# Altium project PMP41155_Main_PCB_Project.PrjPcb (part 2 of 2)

## Sheet PMP41155_Main_Control.SchDoc
size 431 x 279 mm; Date: Not shown in title block; ApprovedBy: Not shown in title block; CheckedBy: Not shown in title block; Author: Not shown in title block; CompanyName: Not shown in title block; Engineer: Not shown in title block; Organization: Not shown in title block; Address1: Not shown in title block; Address2: Not shown in title block; Address3: Not shown in title block; Address4: Not shown in title block; DocumentNumber: 2; Revision: Use project parameter SCH_Rev; SheetNumber: 4; SheetTotal: 5; PageSetup: Record=PageOptions¦CenterHorizontal=True¦CenterVertical=True¦PrintScale=1.00¦XCorrection=1.00¦YCorrection=1.00¦PrintKind=0¦BorderSize=5000000¦LeftOffset=0¦BottomOffset=0¦Orientation=2¦PaperLength=1000¦PaperWidth=1000¦Scale=100¦PaperSource=15¦PrintQuality=600¦MediaType=1¦DitherType=10¦PaperKind=Letter¦PrintScaleMode=1
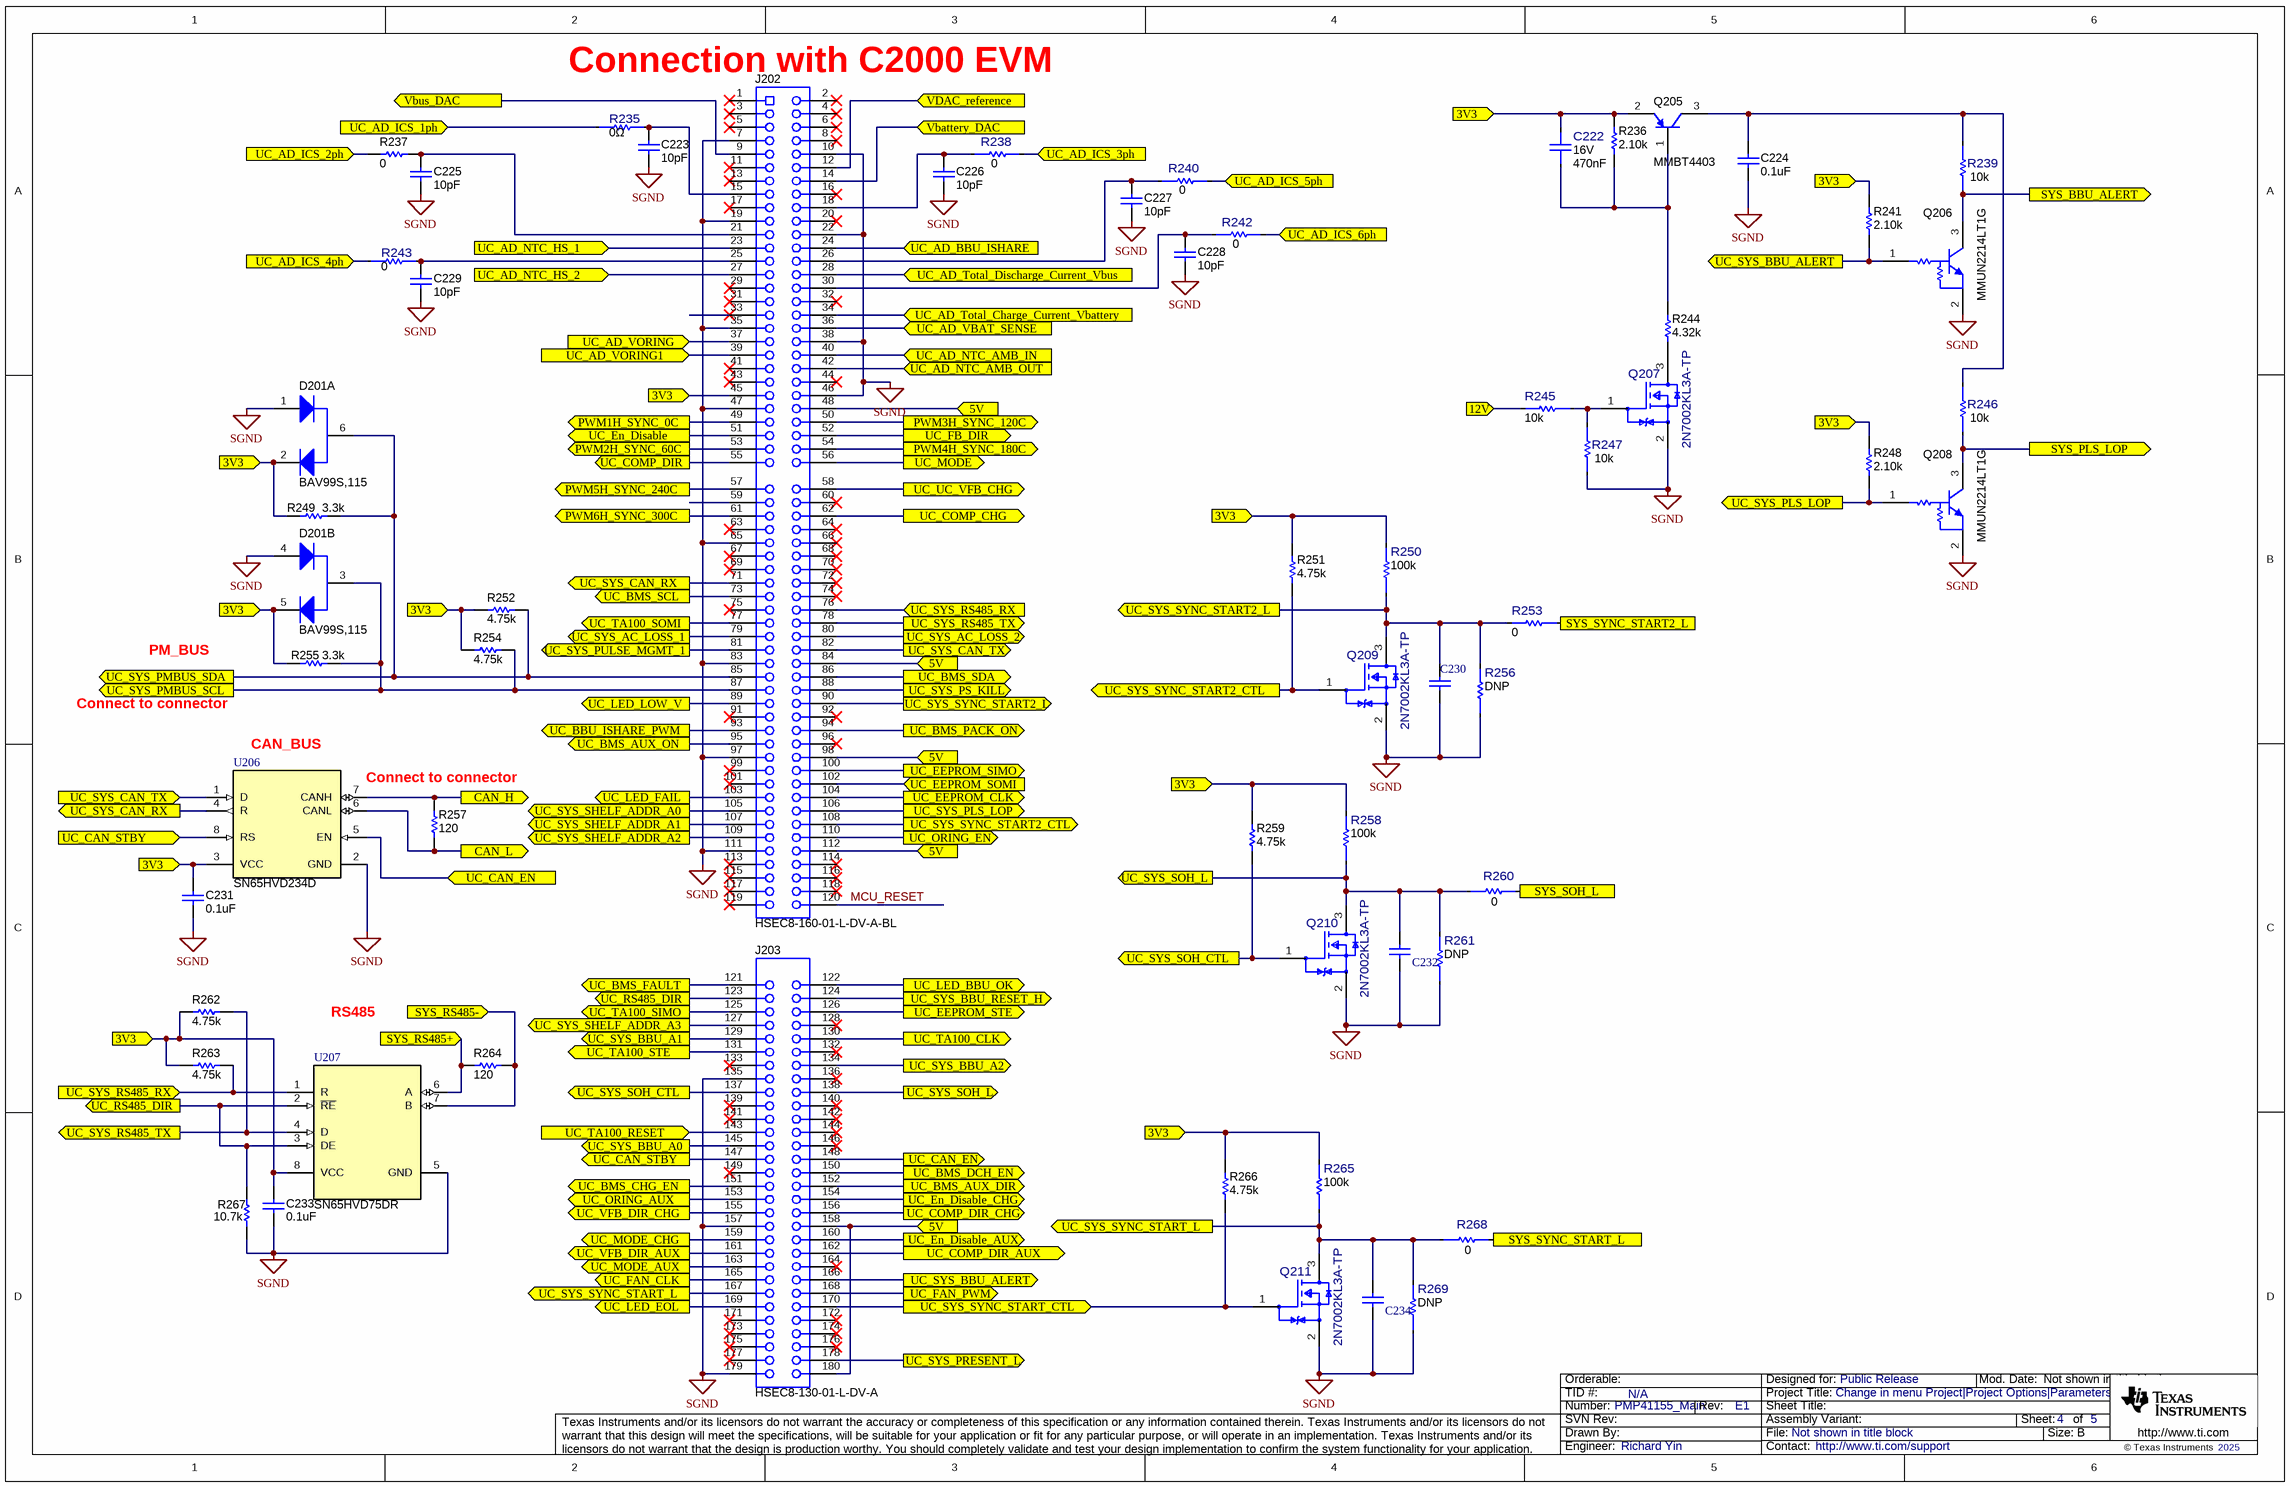
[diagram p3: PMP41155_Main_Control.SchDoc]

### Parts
C222  VDC_V: 16V  Cap_F: 470nF  [FP-C0603C474K4RAC7867_0603-MFG]  (hidden comment: C0603C474K4RAC7867)
C223  ValueDisplayed: 10pF  [0603]  (hidden comment: 0603ZC100KAT2A)
C224  ValueDisplayed: 0.1uF  [0402]  (hidden comment: CMP-0006623-2)
C225  ValueDisplayed: 10pF  [0603]  (hidden comment: 0603ZC100KAT2A)
C226  ValueDisplayed: 10pF  [0603]  (hidden comment: 0603ZC100KAT2A)
C227  ValueDisplayed: 10pF  [0603]  (hidden comment: 0603ZC100KAT2A)
C228  ValueDisplayed: 10pF  [0603]  (hidden comment: 0603ZC100KAT2A)
C229  ValueDisplayed: 10pF  [0603]  (hidden comment: 0603ZC100KAT2A)
C230  885012205001  [WCAP-CSGP_0402_L1W0.5H0.5]  (value not drawn)
C231  ValueDisplayed: 0.1uF  [0402]  (hidden comment: CMP-0006623-2)
C232  885012205001  [WCAP-CSGP_0402_L1W0.5H0.5]  (value not drawn)
C233  ValueDisplayed: 0.1uF  [0402]  (hidden comment: CMP-0006623-2)
C234  885012205001  [WCAP-CSGP_0402_L1W0.5H0.5]  (value not drawn)
D201  BAV99S,115  [SOT-363]  (parts A,B of 2)
J202  HSEC8-160-01-L-DV-A-BL  [controlCARD-120HSEC]
J203  HSEC8-130-01-L-DV-A  [controlCARD-180HSEC-60pinAddon]
Q205  MMBT4403  [SOT-23]
Q206  MMUN2214LT1G  [SOT-23]
Q207  2N7002KL3A-TP  [FP-2N7002KL3A-TP_DFN3-MFG]
Q208  MMUN2214LT1G  [SOT-23]
Q209  2N7002KL3A-TP  [FP-2N7002KL3A-TP_DFN3-MFG]
Q210  2N7002KL3A-TP  [FP-2N7002KL3A-TP_DFN3-MFG]
Q211  2N7002KL3A-TP  [FP-2N7002KL3A-TP_DFN3-MFG]
R235  value 0Ω  [FP-CR0603-10W-000T_0603-MFG]  (hidden comment: CR0603-10W-000T)
R236  ValueDisplayed: 2.10k  [0402]  (hidden comment: CRCW04022K10FKED)
R237  ValueDisplayed: 0  [0603]  (hidden comment: RC0603JR-070RL)
R238  Res_ohm: 0  [FP-CR0201PM0RS001_0201-MFG]  (hidden comment: CR0201PM0RS001)
R239  Res_ohm: 10k  [FP-ERJ-U02F1002X_0402-MFG]  (hidden comment: ERJ-U02F1002X)
R240  Res_ohm: 0  [FP-CR0201PM0RS001_0201-MFG]  (hidden comment: CR0201PM0RS001)
R241  ValueDisplayed: 2.10k  [0402]  (hidden comment: CRCW04022K10FKED)
R242  Res_ohm: 0  [FP-CR0201PM0RS001_0201-MFG]  (hidden comment: CR0201PM0RS001)
R243  value 0  [FP-WSL060300000ZEA9_0603-MFG]  (hidden comment: WSL060300000ZEA9)
R244  ValueDisplayed: 4.32k  [0402]  (hidden comment: CRCW04024K32FKED)
R245  Res_ohm: 10k  [FP-ERJ-U02F1002X_0402-MFG]  (hidden comment: ERJ-U02F1002X)
R246  Res_ohm: 10k  [FP-ERJ-U02F1002X_0402-MFG]  (hidden comment: ERJ-U02F1002X)
R247  Res_ohm: 10k  [FP-ERJ-U02F1002X_0402-MFG]  (hidden comment: ERJ-U02F1002X)
R248  ValueDisplayed: 2.10k  [0402]  (hidden comment: CRCW04022K10FKED)
R249  ValueDisplayed: 3.3k  [0402]  (hidden comment: CRCW04023K30JNED)
R250  Res_ohm: 100k  [FP-RC0402JR-07100KL_0402-MFG]  (hidden comment: RC0402JR-07100KL)
R251  ValueDisplayed: 4.75k  [0603]  (hidden comment: RC0603FR-074K75L)
R252  ValueDisplayed: 4.75k  [0603]  (hidden comment: RC0603FR-074K75L)
R253  Res_ohm: 0  [FP-ERJ-H2G0R00X_0402-MFG]  (hidden comment: ERJ-H2G0R00X)
R254  ValueDisplayed: 4.75k  [0603]  (hidden comment: RC0603FR-074K75L)
R255  ValueDisplayed: 3.3k  [0402]  (hidden comment: CRCW04023K30JNED)
R256  Res_ohm: DNP  [FP-ERJ-H2G0R00X_0402-MFG]  (hidden comment: ERJ-H2G0R00X)
R257  ValueDisplayed: 120  [0402]  (hidden comment: CRCW0402120RJNED)
R258  Res_ohm: 100k  [FP-RC0402JR-07100KL_0402-MFG]  (hidden comment: RC0402JR-07100KL)
R259  ValueDisplayed: 4.75k  [0603]  (hidden comment: RC0603FR-074K75L)
R260  Res_ohm: 0  [FP-JR0805X35E_0805-MFG]  (hidden comment: JR0805X35E)
R261  Res_ohm: DNP  [FP-JR0805X35E_0805-MFG]  (hidden comment: JR0805X35E)
R262  ValueDisplayed: 4.75k  [0603]  (hidden comment: RC0603FR-074K75L)
R263  ValueDisplayed: 4.75k  [0603]  (hidden comment: RC0603FR-074K75L)
R264  ValueDisplayed: 120  [0402]  (hidden comment: CRCW0402120RJNED)
R265  Res_ohm: 100k  [FP-RC0402JR-07100KL_0402-MFG]  (hidden comment: RC0402JR-07100KL)
R266  ValueDisplayed: 4.75k  [0603]  (hidden comment: RC0603FR-074K75L)
R267  ValueDisplayed: 10.7k  [0603]  (hidden comment: RC0603FR-0710K7L)
R268  Res_ohm: 0  [FP-JR0805X35E_0805-MFG]  (hidden comment: JR0805X35E)
R269  Res_ohm: DNP  [FP-JR0805X35E_0805-MFG]  (hidden comment: JR0805X35E)
U206  SN65HVD234D  [D0008A_N]
U207  SN65HVD75DR  [D0008A_N]

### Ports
3V3 (in), 5V (in), 12V (in), CAN_H (out), CAN_L (out), PWM1H_SYNC_0C (out), PWM2H_SYNC_60C (out), PWM3H_SYNC_120C (out), PWM4H_SYNC_180C (out), PWM5H_SYNC_240C (out), PWM6H_SYNC_300C (out), SYS_BBU_ALERT (out), SYS_PLS_LOP (out), SYS_RS485+ (in), SYS_RS485- (in), SYS_SOH_L (out), SYS_SYNC_START2_L (out), SYS_SYNC_START_L (out), UC_AD_BBU_ISHARE (in), UC_AD_ICS_1ph (in), UC_AD_ICS_2ph (in), UC_AD_ICS_3ph (in), UC_AD_ICS_4ph (in), UC_AD_ICS_5ph (in), UC_AD_ICS_6ph (in), UC_AD_NTC_AMB_IN (in), UC_AD_NTC_AMB_OUT (in), UC_AD_NTC_HS_1 (in), UC_AD_NTC_HS_2 (in), UC_AD_Total_Charge_Current_Vbattery (in), UC_AD_Total_Discharge_Current_Vbus (in), UC_AD_VBAT_SENSE (in), UC_AD_VORING1 (in), UC_AD_VORING (in), UC_BBU_ISHARE_PWM (out), UC_BMS_AUX_DIR (out), UC_BMS_AUX_ON (out), UC_BMS_CHG_EN (out), UC_BMS_DCH_EN (out), UC_BMS_FAULT (out), UC_BMS_PACK_ON (out), UC_BMS_SCL (out), UC_BMS_SDA (out), UC_CAN_EN (in), UC_CAN_EN (out), UC_CAN_STBY (in), UC_CAN_STBY (out), UC_COMP_CHG (out), UC_COMP_DIR (out), UC_COMP_DIR_AUX (out), UC_COMP_DIR_CHG (out), UC_EEPROM_CLK (out), UC_EEPROM_SIMO (out), UC_EEPROM_SOMI (in), UC_EEPROM_STE (out), UC_En_Disable (out), UC_En_Disable_AUX (out), UC_En_Disable_CHG (out), UC_FAN_CLK (out), UC_FAN_PWM (out), UC_FB_DIR (out), UC_LED_BBU_OK (out), UC_LED_EOL (out), UC_LED_FAIL (out), UC_LED_LOW_V (out), UC_MODE (out), UC_MODE_AUX (out), UC_MODE_CHG (out), UC_ORING_AUX (out), UC_ORING_EN (out), UC_RS485_DIR (out), UC_SYS_AC_LOSS_1 (out), UC_SYS_AC_LOSS_2 (out), UC_SYS_BBU_A0 (out), UC_SYS_BBU_A1 (out), UC_SYS_BBU_A2 (out), UC_SYS_BBU_ALERT (out), UC_SYS_BBU_RESET_H (out), UC_SYS_CAN_RX (out), UC_SYS_CAN_TX (in), UC_SYS_CAN_TX (out), UC_SYS_PLS_LOP (out), UC_SYS_PMBUS_SCL (out), UC_SYS_PMBUS_SDA (out), UC_SYS_PRESENT_L (out), UC_SYS_PS_KILL (out), UC_SYS_PULSE_MGMT_1 (out), UC_SYS_RS485_RX (in), UC_SYS_RS485_TX (out), UC_SYS_SHELF_ADDR_A0 (out), UC_SYS_SHELF_ADDR_A1 (out), UC_SYS_SHELF_ADDR_A2 (out), UC_SYS_SHELF_ADDR_A3 (out), UC_SYS_SOH_CTL (out), UC_SYS_SOH_L (out), UC_SYS_SYNC_START2_CTL (out), UC_SYS_SYNC_START2_L (out), UC_SYS_SYNC_START_CTL (out), UC_SYS_SYNC_START_L (out), UC_TA100_CLK (out), UC_TA100_RESET (in), UC_TA100_SIMO (out), UC_TA100_SOMI (out), UC_TA100_STE (out), UC_UC_VFB_CHG (out), UC_VFB_DIR_AUX (out), UC_VFB_DIR_CHG (out), Vbattery_DAC (in), Vbus_DAC (out), VDAC_reference (in)

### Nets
SGND: C223.2 C224.2 C225.2 C226.2 C227.2 C228.2 C229.2 C230.1 C231.2 C232.1 C233.2 C234.1 D201.1(A1) D201.4(A3) J202.7 J202.10 J202.19 J202.22 J202.35 J202.38 J202.46 J202.47 J202.65 J202.83 J202.97 J202.111 J203.135 J203.157 J203.179 Q206.2(E) Q207.2(S) Q208.2(E) Q209.2(S) Q210.2(S) Q211.2(S) R247.1 R256.1 R261.1 R267.1 R269.1 U206.2(GND) U207.5(GND)
3V3: C222.2 C231.1 C233.1 D201.2(K2) D201.5(K4) J202.45 Q205.2(E) R236.2 R241.2 R248.2 R249.1 R250.2 R251.2 R252.2 R254.2 R255.1 R258.2 R259.2 R262.2 R263.2 R265.2 R266.2 U206.3(VCC) U207.8(VCC) ; port 3V3
5V: J202.48 J202.84 J202.98 J202.112 J203.158 J203.180 ; port 5V
12V: R245.2 ; port 12V
CAN_H: R257.2 U206.7(CANH) ; port CAN_H
CAN_L: R257.1 U206.6(CANL) ; port CAN_L
MCU_RESET: J202.120
PWM1H_SYNC_0C: J202.49 ; port PWM1H_SYNC_0C
PWM2H_SYNC_60C: J202.53 ; port PWM2H_SYNC_60C
PWM3H_SYNC_120C: J202.50 ; port PWM3H_SYNC_120C
PWM4H_SYNC_180C: J202.54 ; port PWM4H_SYNC_180C
PWM5H_SYNC_240C: J202.57 ; port PWM5H_SYNC_240C
PWM6H_SYNC_300C: J202.61 ; port PWM6H_SYNC_300C
SYS_BBU_ALERT: Q206.3(C) R239.1 ; port SYS_BBU_ALERT
SYS_PLS_LOP: Q208.3(C) R246.1 ; port SYS_PLS_LOP
SYS_RS485+: R264.2 U207.6(A) ; port SYS_RS485+
SYS_RS485-: R264.1 U207.7(B) ; port SYS_RS485-
SYS_SOH_L: R260.2 ; port SYS_SOH_L
SYS_SYNC_START2_L: R253.1 ; port SYS_SYNC_START2_L
SYS_SYNC_START_L: R268.2 ; port SYS_SYNC_START_L
UC_AD_BBU_ISHARE: J202.24 ; port UC_AD_BBU_ISHARE
UC_AD_ICS_1ph: R235.1 ; port UC_AD_ICS_1ph
UC_AD_ICS_2ph: R237.1 ; port UC_AD_ICS_2ph
UC_AD_ICS_3ph: R238.2 ; port UC_AD_ICS_3ph
UC_AD_ICS_4ph: R243.1 ; port UC_AD_ICS_4ph
UC_AD_ICS_5ph: R240.2 ; port UC_AD_ICS_5ph
UC_AD_ICS_6ph: R242.2 ; port UC_AD_ICS_6ph
UC_AD_NTC_AMB_IN: J202.40 ; port UC_AD_NTC_AMB_IN
UC_AD_NTC_AMB_OUT: J202.42 ; port UC_AD_NTC_AMB_OUT
UC_AD_NTC_HS_1: J202.23 ; port UC_AD_NTC_HS_1
UC_AD_NTC_HS_2: J202.27 ; port UC_AD_NTC_HS_2
UC_AD_Total_Charge_Current_VBattery: J202.34 ; port UC_AD_Total_Charge_Current_Vbattery
UC_AD_Total_Discharge_Current_VBus: J202.28 ; port UC_AD_Total_Discharge_Current_Vbus
UC_AD_VBAT_SENSE: J202.36 ; port UC_AD_VBAT_SENSE
UC_AD_VORING: J202.37 ; port UC_AD_VORING
UC_AD_VORING1: J202.39 ; port UC_AD_VORING1
UC_BBU_ISHARE_PWM: J202.93 ; port UC_BBU_ISHARE_PWM
UC_BMS_AUX_DIR: J203.152 ; port UC_BMS_AUX_DIR
UC_BMS_AUX_ON: J202.95 ; port UC_BMS_AUX_ON
UC_BMS_CHG_EN: J203.151 ; port UC_BMS_CHG_EN
UC_BMS_DCH_EN: J203.150 ; port UC_BMS_DCH_EN
UC_BMS_FAULT: J203.121 ; port UC_BMS_FAULT
UC_BMS_PACK_ON: J202.94 ; port UC_BMS_PACK_ON
UC_BMS_SCL: J202.73 ; port UC_BMS_SCL
UC_BMS_SDA: J202.86 ; port UC_BMS_SDA
UC_CAN_EN: J203.148 U206.5(EN) ; port UC_CAN_EN
UC_CAN_STBY: J203.147 U206.8(RS) ; port UC_CAN_STBY
UC_COMP_CHG: J202.62 ; port UC_COMP_CHG
UC_COMP_DIR: J202.55 ; port UC_COMP_DIR
UC_COMP_DIR_AUX: J203.162 ; port UC_COMP_DIR_AUX
UC_COMP_DIR_CHG: J203.156 ; port UC_COMP_DIR_CHG
UC_EEPROM_CLK: J202.104 ; port UC_EEPROM_CLK
UC_EEPROM_SIMO: J202.100 ; port UC_EEPROM_SIMO
UC_EEPROM_SOMI: J202.102 ; port UC_EEPROM_SOMI
UC_EEPROM_STE: J203.126 ; port UC_EEPROM_STE
UC_En_Disable: J202.51 ; port UC_En_Disable
UC_En_Disable_AUX: J203.160 ; port UC_En_Disable_AUX
UC_En_Disable_CHG: J203.154 ; port UC_En_Disable_CHG
UC_FAN_CLK: J203.165 ; port UC_FAN_CLK
UC_FAN_PWM: J203.168 ; port UC_FAN_PWM
UC_FB_DIR: J202.52 ; port UC_FB_DIR
UC_LED_BBU_OK: J203.122 ; port UC_LED_BBU_OK
UC_LED_EOL: J203.169 ; port UC_LED_EOL
UC_LED_FAIL: J202.103 ; port UC_LED_FAIL
UC_LED_LOW_V: J202.89 ; port UC_LED_LOW_V
UC_MODE: J202.56 ; port UC_MODE
UC_MODE_AUX: J203.163 ; port UC_MODE_AUX
UC_MODE_CHG: J203.159 ; port UC_MODE_CHG
UC_ORING_AUX: J203.153 ; port UC_ORING_AUX
UC_ORING_EN: J202.110 ; port UC_ORING_EN
UC_RS485_DIR: J203.123 R267.2 U207.2(~{RE}) U207.3(DE) ; port UC_RS485_DIR
UC_SYS_AC_LOSS_1: J202.79 ; port UC_SYS_AC_LOSS_1
UC_SYS_AC_LOSS_2: J202.80 ; port UC_SYS_AC_LOSS_2
UC_SYS_BBU_A0: J203.145 ; port UC_SYS_BBU_A0
UC_SYS_BBU_A1: J203.129 ; port UC_SYS_BBU_A1
UC_SYS_BBU_A2: J203.134 ; port UC_SYS_BBU_A2
UC_SYS_BBU_ALERT: J203.166 Q206.1(B) R241.1 ; port UC_SYS_BBU_ALERT
UC_SYS_BBU_RESET_H: J203.124 ; port UC_SYS_BBU_RESET_H
UC_SYS_CAN_RX: J202.71 U206.4(R) ; port UC_SYS_CAN_RX
UC_SYS_CAN_TX: J202.82 U206.1(D) ; port UC_SYS_CAN_TX
UC_SYS_PLS_LOP: J202.106 Q208.1(B) R248.1 ; port UC_SYS_PLS_LOP
UC_SYS_PMBUS_SCL: D201.3(K3A4) J202.87 R254.1 R255.2 ; port UC_SYS_PMBUS_SCL
UC_SYS_PMBUS_SDA: D201.6(K1A2) J202.85 R249.2 R252.1 ; port UC_SYS_PMBUS_SDA
UC_SYS_Present_L: J203.178 ; port UC_SYS_PRESENT_L
UC_SYS_PS_KILL: J202.88 ; port UC_SYS_PS_KILL
UC_SYS_PULSE_MGMT_1: J202.81 ; port UC_SYS_PULSE_MGMT_1
UC_SYS_RS485_RX: J202.76 R263.1 U207.1(R) ; port UC_SYS_RS485_RX
UC_SYS_RS485_TX: J202.78 R262.1 U207.4(D) ; port UC_SYS_RS485_TX
UC_SYS_SHELF_ADDR_A0: J202.105 ; port UC_SYS_SHELF_ADDR_A0
UC_SYS_SHELF_ADDR_A1: J202.107 ; port UC_SYS_SHELF_ADDR_A1
UC_SYS_SHELF_ADDR_A2: J202.109 ; port UC_SYS_SHELF_ADDR_A2
UC_SYS_SHELF_ADDR_A3: J203.127 ; port UC_SYS_SHELF_ADDR_A3
UC_SYS_SOH_CTL: J203.137 Q210.1(G) R259.1 ; port UC_SYS_SOH_CTL
UC_SYS_SOH_L: C232.2 J203.138 Q210.3(D) R258.1 R260.1 R261.2 ; port UC_SYS_SOH_L
UC_SYS_SYNC_START2_CTL: J202.108 Q209.1(G) R251.1 ; port UC_SYS_SYNC_START2_CTL
UC_SYS_SYNC_START2_L: C230.2 J202.90 Q209.3(D) R250.1 R253.2 R256.2 ; port UC_SYS_SYNC_START2_L
UC_SYS_SYNC_START_CTL: J203.170 Q211.1(G) R266.1 ; port UC_SYS_SYNC_START_CTL
UC_SYS_SYNC_START_L: C234.2 J203.167 Q211.3(D) R265.1 R268.1 R269.2 ; port UC_SYS_SYNC_START_L
UC_TA100_CLK: J203.130 ; port UC_TA100_CLK
UC_TA100_RESET: J203.143 ; port UC_TA100_RESET
UC_TA100_SIMO: J203.125 ; port UC_TA100_SIMO
UC_TA100_SOMI: J202.77 ; port UC_TA100_SOMI
UC_TA100_STE: J203.131 ; port UC_TA100_STE
UC_UC_VFB_CHG: J202.58 ; port UC_UC_VFB_CHG
UC_VFB_DIR_AUX: J203.161 ; port UC_VFB_DIR_AUX
UC_VFB_DIR_CHG: J203.155 ; port UC_VFB_DIR_CHG
Vbattery_DAC: J202.14 ; port Vbattery_DAC
Vbus_DAC: J202.9 ; port Vbus_DAC
VDAC_reference: J202.12 ; port VDAC_reference
NetC222_1: C222.1 Q205.1(B) R236.1 R244.2
NetC223_1: C223.1 J202.15 R235.2
NetC224_1: C224.1 Q205.3(C) R239.2 R246.2
NetC225_1: C225.1 J202.21 R237.2
NetC226_1: C226.1 J202.18 R238.1
NetC227_1: C227.1 J202.26 R240.1
NetC228_1: C228.1 J202.30 R242.1
NetC229_1: C229.1 J202.25 R243.2
NetQ207_1: Q207.1(G) R245.1 R247.2
NetQ207_3: Q207.3(D) R244.1

Not connected (* = marked no-connect by the designer): J202 1* 2* 3* 4* 5* 6* 8* 11* 13* 16* 17* 20* 29* 31* 32* 33* 41* 43* 44* 59 60* 63* 64* 66* 67* 68* 69* 70* 72* 74* 75* 91* 92* 96* 99* 101* 113* 114* 115* 116* 117* 118* 119*; J203 128* 132* 133* 136* 139* 140* 141* 142* 144* 146* 149* 164* 171* 172* 173* 174* 175* 176* 177*

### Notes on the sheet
- (near J202) Connection with C2000 EVM
- Connect to connector
- PM_BUS
- CAN_BUS
- RS485

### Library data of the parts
C222 = CMP-0095164-1: 0.47 µF ±10% 16V Ceramic Capacitor X7R 0603 (1608 Metric); Manufacturer: KEMET; Value: 470nF; TempCo: 15%; AEC Qualified: No; ValueDisplayed: 0.47uF; SizeZ_mm: 0.87mm
C223 C225-C229 = CMP-0006811-4: CAP, CERM, 10 pF, 10 V, +/- 10%, X7R, 0603; Manufacturer: AVX; Polarized: N; Value: 10pF; U/M: EA; Value1: Unknown; VDC_V: 10V; TaMin_C: -55°C; TaMax_C: 125°C; SizeArea_mm2: 1.28; SizeAreaWB_mm2: 4.68; SizeX_mm: 1.6; SizeY_mm: 0.8; SizeZ_mm: 1; AEC Category: Q200
C224 C231 C233 = CMP-0006623-2: CAP, CERM, 0.1 uF, 6.3 V, +/- 10%, X7R, 0402; PartNumber: GRM155R70J104KA01D; Manufacturer: MuRata; Polarized: N; Value: 0.1uF; U/M: EA; Cap_F: 100nF; Value1: Unknown; VDC_V: 6.3V; TaMin_C: -55°C; TaMax_C: 125°C; SizeAreaWB_mm2: 3; SizeZ_mm: 0.6; SizeX_mm: 1; SizeY_mm: 0.5; AEC Category: Q200
C230 C232 C234 = CMP-0115312-1: WCAP-CSGP Multilayer Ceramic Chip Capacitor, General Purpose, size 0402, X7R, 100pF, 10VDC; Manufacturer: Wurth Elektronik; Capacitance Tolerance: +/-10%; Case/Size Code: 0402; Dissipation Factor: 5%; Insulation Resistance: 10GOhm; Rated Voltage (DC): 10V; Technical Reference: X7R0402101K010DFCT10000
D201 = CMP-0076927-2: Diode, Switching, 100 V, 0.2 A, SOT-363; Manufacturer: Nexperia; Vf_V: 1.25V; Green_Lifecycle: Not Set; Green_REACh: Incomplete; Io_A: 200mA; SizeArea_mm2: 4.84; Value1: 0.2A; TJmax_C: 150°C; SizeAreaWB_mm2: 10.24; Value: 100V; SizeX_mm: 2.2; AEC Category: Q101; SizeZ_mm: 1.1
J202 = CMP-0003814-2: C2000 controlCARD-120HSEC connector, SMT; Manufacturer: Samtec; Note: The pin numbering does not match Samtec datasheet
J203 = CMP-0003859-2: C2000 controlCARD-180HSEC (60-pin addon) connector, SMT; Manufacturer: Samtec; Note: The pin numbering does not match Samtec datasheet
Q205 = CMP-0000327-2: Transistor, PNP, 40 V, 0.6 A, SOT-23; Manufacturer: Fairchild Semiconductor; TaMax_C: 150°C; Value2: 500; Value1: 0.6 A; Vcesat1_V: 750mV; SizeX_mm: 2.5; SizeY_mm: 3; TaMin_C: -55°C; IcRated_A: 600mA; CompType: BJT; SizeZ_mm: 1.1; Value: 40 V; SizeArea_mm2: 7.5; NPN: 0; Vceo_V: 40V; PNP: 1; AEC Category: Q101; SizeAreaWB_mm2: 14; U/M: EA
Q206 Q208 = CMP-0000511-2: Transistor, NPN, 50 V, 0.1 A, AEC-Q101, SOT-23; Manufacturer: ON Semiconductor; TaMax_C: 150°C; Value1: 0.1 A; Vcesat1_V: 250mV; SizeX_mm: 2.5; SizeY_mm: 3; TaMin_C: -55°C; IcRated_A: 100mA; CompType: BJT; SizeZ_mm: 1.1; AEC Qualified: Y; Value: 50 V; SizeArea_mm2: 7.5; NPN: 1; Vceo_V: 50V; PNP: 0; AEC Category: Q101; SizeAreaWB_mm2: 14; U/M: EA
Q207 Q209-Q211 = CMP-0043768-1: N-Channel 60 V 260mA (Ta) 200mW Surface Mount DFN1006-3; Manufacturer: MCC; AEC Qualified: No; QgTyp_nC: 1.22nC @ 10V; Rdson45_ohm: 1.9; SizeZ_mm: 0.55mm; VdsMax_V: 1.2V; Vgs_V: 20V; ChMode: False; Drain To Source Breakdown Voltage: 60V; Input Capacitace At Vds: 21pF @ 30V; Number Of Channels: 1; Power_W: 0.2W; Pulse Drain Current: 1.3A; Reverse Recovery Charge: 3.6nC; Reverse Recovery Time: 16ns; Rthja Max: 600°C/W; Standoff Height: 0mm; Threshold Vgs Max: 2.5V; Threshold Vgs Min: 1V; TJmax_C: +150°C; Transconductance: 0.13S; Turn Off Delay Time: 20ns; Turn On Delay Time: 7ns; Typ Forward Diode Voltage: 0.9V
R235 = CMP-0094956-1: 0 Ohms Jumper 0.1W, 1/10W Chip Resistor 0603 (1608 Metric) - Thick Film; Manufacturer: Venkel; Res_ohm: 0; Power_W: 100mW; SizeZ_mm: 0.55mm; AEC Qualified: No
R236 R241 R248 = CMP-0026229-2: RES, 2.10 k, 1%, 0.063 W, AEC-Q200 Grade 0, 0402; Manufacturer: Vishay-Dale; Power_W: 63mW; TempCo: 100 ppm/C; Value_Code: 2k10; Value: 2.10k; EIA_Code: E96; Res_ohm: 2.1k; SizeX_mm: 1; SizeY_mm: 0.5; SizeZ_mm: 0.6; Value2: 0.063W; AEC Qualified: Y; VDC_V: 50V; AEC Category: Q200; AEC Grade: 0
R237 = RC0603JR-070RL: RES, 0, 5%, 0.1 W, 0603; Manufacturer: Yageo America; CompType: Resistor; Value: 0; Value_Code: 0000; Tolerance_%: 5; Power_W: 0.1; Value2: 0.1W; VDC_V: 50; TempCo: 200 ppm/C; SizeArea_mm2: 1.28; SizeX_mm: 1.6; SizeY_mm: 0.8; SizeZ_mm: 1; EIA_Code: E24; U/M: EA; AEC Category: Q200; Green_Lifecycle: Active; Green_REACh: Passed
R238 R240 R242 = CMP-0124663-1: 0 Ohms Jumper 0.05W, 1/20W Chip Resistor 0201 (0603 Metric) Thick Film; Manufacturer: NextGen Components; Value: 0; Power_W: 50mW; VDC_V: 25V; SizeZ_mm: 0.26mm; AEC Qualified: No
R239 R245-R247 = CMP-0120043-1: 10 kOhms ±1% 0.1W, 1/10W Chip Resistor 0402 (1005 Metric) Anti-Sulfur, Automotive AEC-Q200 Thick Film; Manufacturer: Panasonic; AEC Grade: Grade 0; AEC Qualified: Yes; Power_W: 100mW; SizeZ_mm: 0.4mm; TempCo: 200ppm/°C; VDC_V: 50V; Value: 10k
R243 = CMP-0031931-1: 0 Ohms Jumper Chip Resistor 0603 (1608 Metric) Metal Element; Manufacturer: Vishay; TempCo: 3900ppm/°C; SizeZ_mm: 0.457mm; AEC Qualified: No
R244 = CMP-0026408-2: RES, 4.32 k, 1%, 0.063 W, AEC-Q200 Grade 0, 0402; Manufacturer: Vishay-Dale; Power_W: 63mW; TempCo: 100 ppm/C; Value_Code: 4k32; Value: 4.32k; EIA_Code: E96; SizeX_mm: 1; SizeY_mm: 0.5; SizeZ_mm: 0.6; Value2: 0.063W; AEC Qualified: Y; VDC_V: 50V; AEC Category: Q200; AEC Grade: 0
R249 R255 = CMP-0026918-5: RES, 3.3 k, 5%, 0.063 W, AEC-Q200 Grade 0, 0402; Manufacturer: Vishay-Dale; Power_W: 63mW; TempCo: 200 ppm/C; Value_Code: 3k30; Value: 3.3k; EIA_Code: E24; SizeX_mm: 1; SizeY_mm: 0.5; SizeZ_mm: 0.6; Value2: 0.063W; AEC Qualified: Y; VDC_V: 50V; AEC Category: Q200; AEC Grade: 0
R250 R258 R265 = CMP-0094182-1: 100 kOhms ±5% 0.063W, 1/16W Chip Resistor 0402 (1005 Metric) Moisture Resistant Thick Film; Manufacturer: YAGEO; Power_W: 63mW; AEC Qualified: No; TempCo: 100ppm/°C; Value: 100k; VDC_V: 50V; SizeZ_mm: 0.4mm
R251 R252 R254 R259 R262 R263 R266 = CMP-0023152-5: RES, 4.75 k, 1%, 0.1 W, 0603; Manufacturer: Yageo; Value: 4.75k; Value_Code: 4k75; Power_W: 100mW; Value2: 0.1W; VDC_V: 75V; TempCo: 100 ppm/C; SizeArea_mm2: 1.28; SizeX_mm: 1.6; SizeY_mm: 0.8; SizeZ_mm: 1; EIA_Code: E96; AEC Category: Q200; AEC Qualified: N; SizeAreaWB_mm2: 4.68
R253 R256 = CMP-0121543-1: 0 Ohms Jumper Chip Resistor 0402 (1005 Metric) Automotive AEC-Q200 Thick Film; Manufacturer: Panasonic; AEC Grade: Grade 0; AEC Qualified: Yes; SizeZ_mm: 0.4mm; VDC_V: 50V; Value: 0
R257 R264 = CMP-0026833-3: RES, 120, 5%, 0.063 W, AEC-Q200 Grade 0, 0402; Manufacturer: Vishay-Dale; Power_W: 63mW; TempCo: 200 ppm/C; Value_Code: 120R; Value: 120; EIA_Code: E24; SizeX_mm: 1; SizeY_mm: 0.5; SizeZ_mm: 0.6; Value2: 0.063W; AEC Qualified: Y; VDC_V: 50V; AEC Category: Q200; AEC Grade: 0
R260 R261 R268 R269 = CMP-0096818-1: 0 Ohms Jumper 0.245W Chip Resistor 0805 (2012 Metric) - Metal Element; Manufacturer: Ohmite; AEC Qualified: No; Value: 0; Power_W: 245mW; SizeZ_mm: 0.55mm
R267 = CMP-0022745-5: RES, 10.7 k, 1%, 0.1 W, 0603; Manufacturer: Yageo; Value: 10.7k; Value_Code: 10k7; Power_W: 100mW; Value2: 0.1W; VDC_V: 75V; TempCo: 100 ppm/C; SizeArea_mm2: 1.28; SizeX_mm: 1.6; SizeY_mm: 0.8; SizeZ_mm: 1; EIA_Code: E96; AEC Category: Q200; AEC Qualified: N; SizeAreaWB_mm2: 4.68
U206 = CMP-0033354-1: 3.3V CAN Transceiver with Sleep Mode, 6 mA, -40 to 125 degC, 8-pin SOIC (D), Green (RoHS & no Sb/Br); Manufacturer: Texas Instruments; Receivers Per Package: 1; ICC(Max)(mA): 6; Bus Fault Voltage(V): +/-30; Supply Voltage(s)(V): 3.3; Rating: Catalog; Transient Pulse Protection(V): -100 to 100
U207 = CMP-0029827-1: 3.3 V Supply RS-485 with IEC ESD Protection, 20 Mbps, -40 to 125 degC, 8-Pin SOIC, RoHS, Tape and Reel; Manufacturer: Texas Instruments; Signaling Rate (Max) (Mbps): 20; VCC: 3 to 3.6 V; ESD: 15 kV; VI: -7 to 12 V; ICC (Max) (mA): 0.95; No. of RX: 1

## Sheet PMP41155_Main_Connection.SchDoc
size 431 x 279 mm; Date: Not shown in title block; ApprovedBy: Not shown in title block; CheckedBy: Not shown in title block; Author: Not shown in title block; CompanyName: Not shown in title block; Engineer: Not shown in title block; Organization: Not shown in title block; Address1: Not shown in title block; Address2: Not shown in title block; Address3: Not shown in title block; Address4: Not shown in title block; DocumentNumber: 3; Revision: Use project parameter SCH_Rev; SheetNumber: 5; SheetTotal: 5; PageSetup: Record=PageOptions¦CenterHorizontal=True¦CenterVertical=True¦PrintScale=1.00¦XCorrection=1.00¦YCorrection=1.00¦PrintKind=0¦BorderSize=5000000¦LeftOffset=0¦BottomOffset=0¦Orientation=2¦PaperLength=1000¦PaperWidth=1000¦Scale=100¦PaperSource=15¦PrintQuality=600¦MediaType=1¦DitherType=10¦PaperKind=Letter¦PrintScaleMode=1
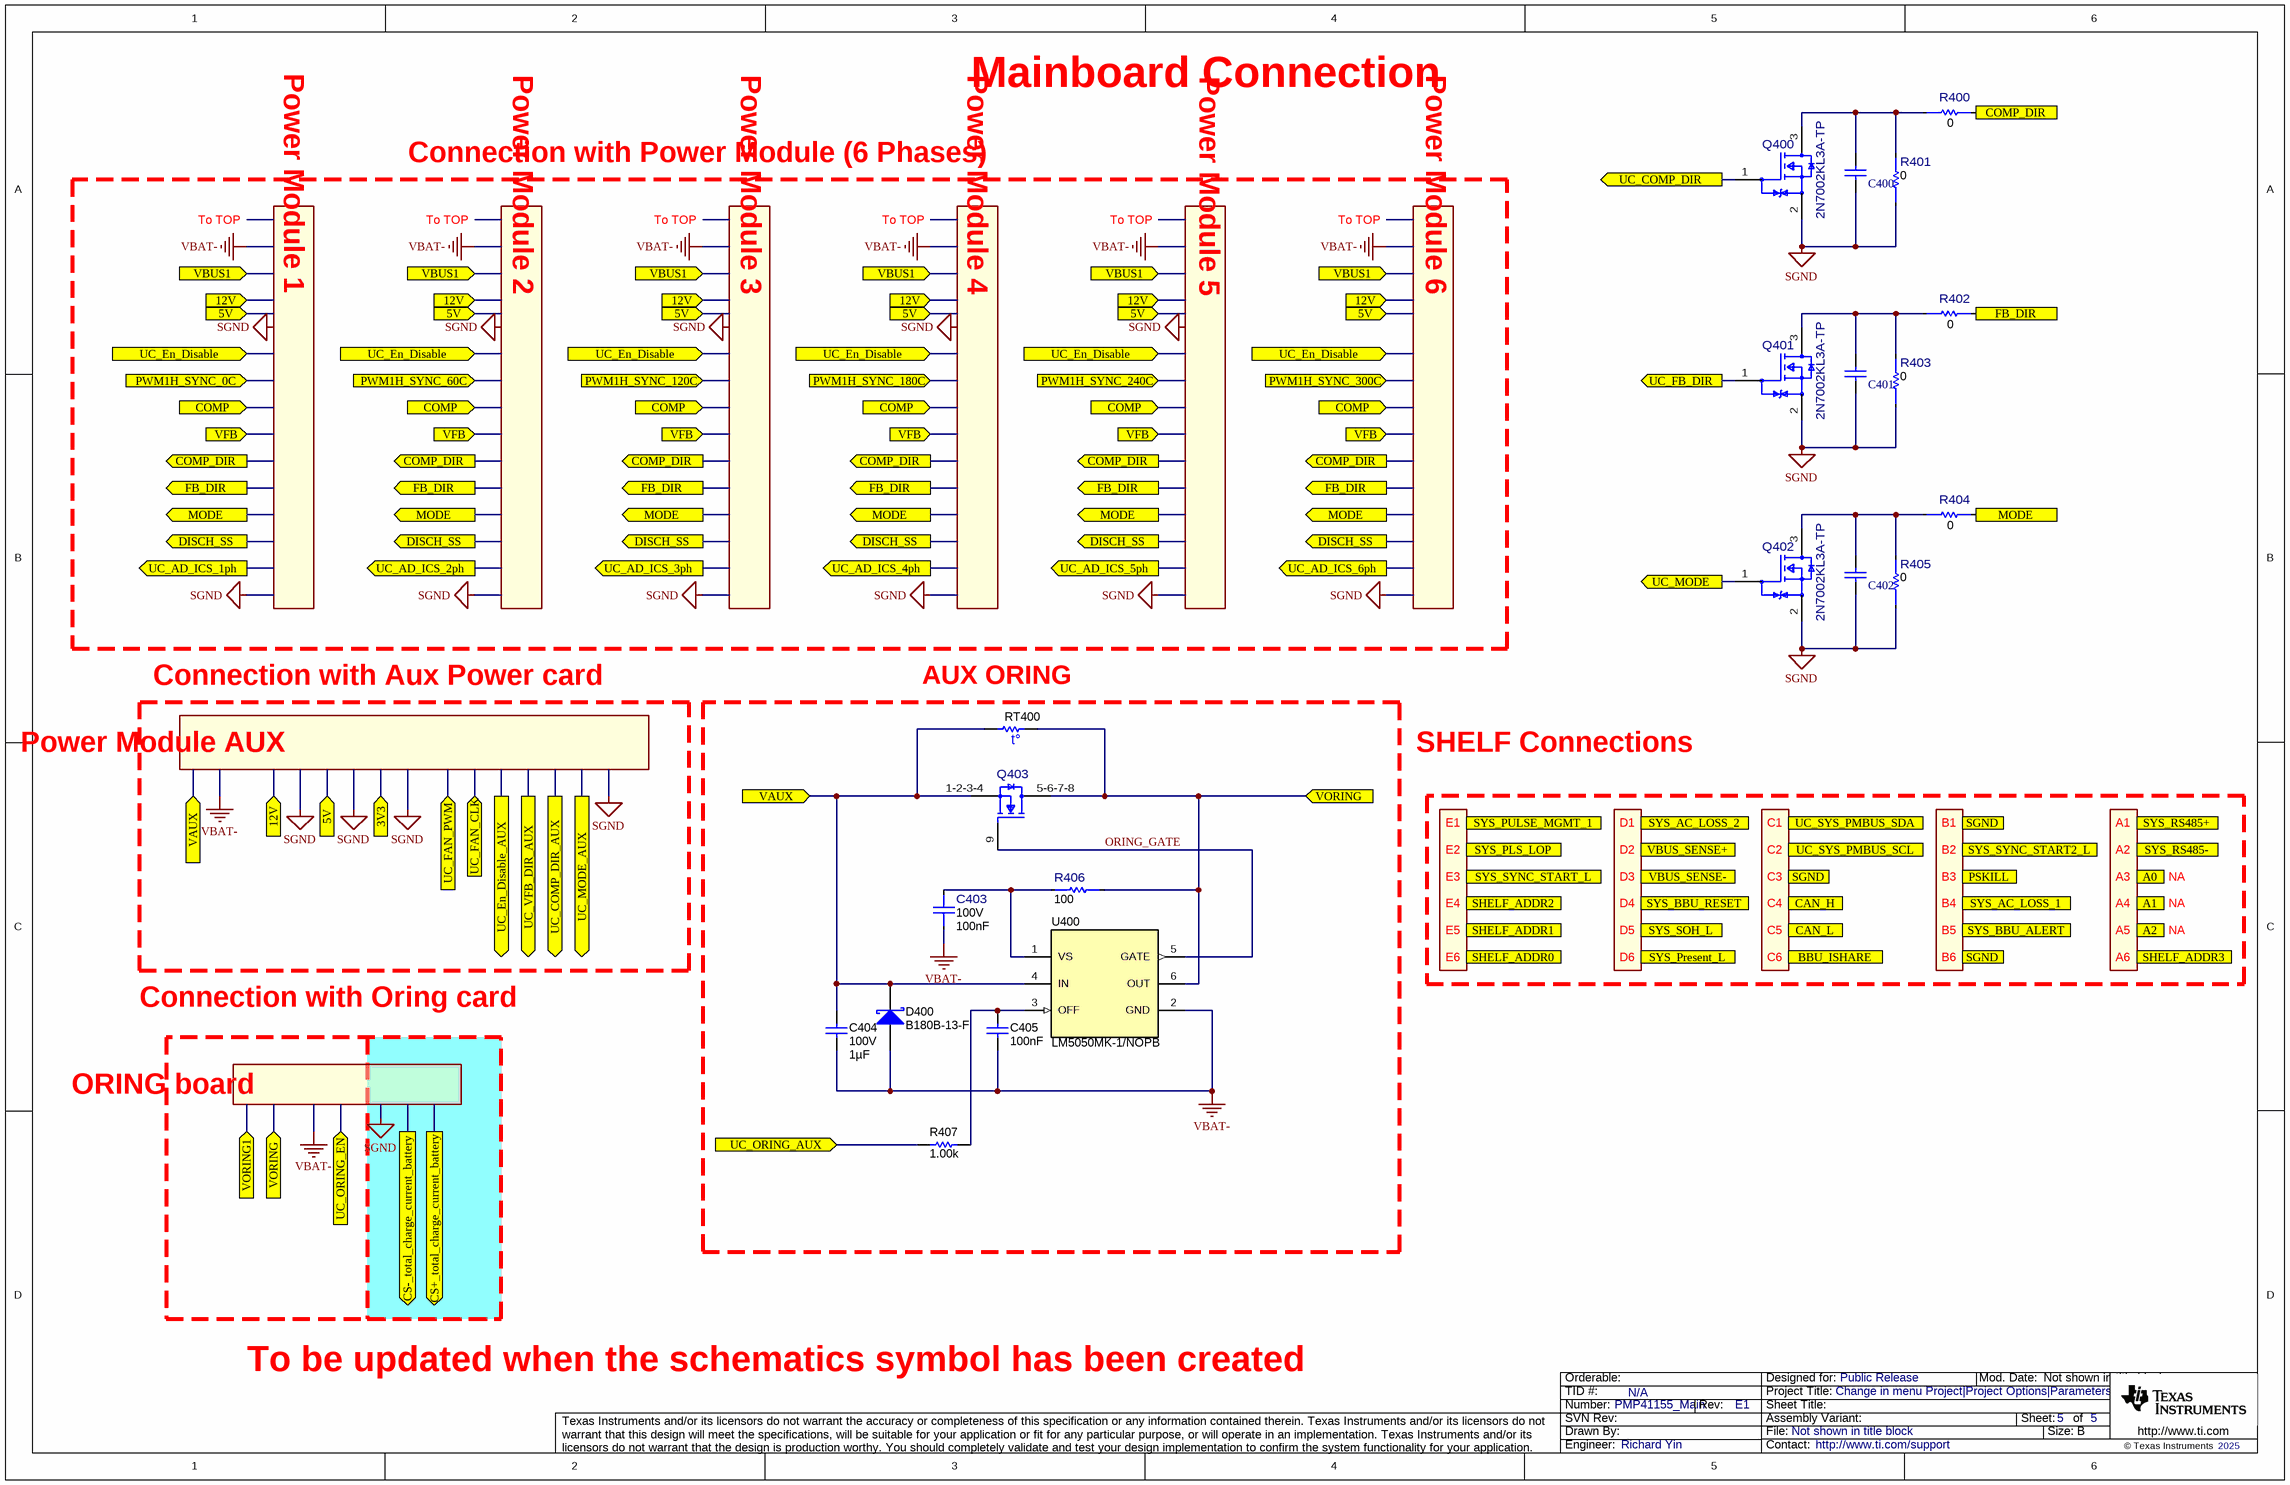
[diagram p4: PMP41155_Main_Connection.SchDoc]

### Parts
C400  885012205001  [WCAP-CSGP_0402_L1W0.5H0.5]  (value not drawn)
C401  885012205001  [WCAP-CSGP_0402_L1W0.5H0.5]  (value not drawn)
C402  885012205001  [WCAP-CSGP_0402_L1W0.5H0.5]  (value not drawn)
C403  VDC_V: 100V  Cap_F: 100nF  [FP-885012206120_0603-MFG]  (hidden comment: 885012206120)
C404  VDC_V: 100V  Cap_F: 1µF  [0805_150]  (hidden comment: KAF21KR72A105KU)
C405  Cap_F: 100nF  [0603]  (hidden comment: GRM188R71E104KA01D)
D400  B180B-13-F  [SMB]
Q400  2N7002KL3A-TP  [FP-2N7002KL3A-TP_DFN3-MFG]
Q401  2N7002KL3A-TP  [FP-2N7002KL3A-TP_DFN3-MFG]
Q402  2N7002KL3A-TP  [FP-2N7002KL3A-TP_DFN3-MFG]
Q403  IQD016N08NM5CGATMA1  [FP-IQD016N08NM5CGATMA1_TTFN-9-MFG]  (value not drawn)
R400  Res_ohm: 0  [FP-JR0805X35E_0805-MFG]  (hidden comment: JR0805X35E)
R401  Res_ohm: 0  [FP-JR0805X35E_0805-MFG]  (hidden comment: JR0805X35E)
R402  Res_ohm: 0  [FP-JR0805X35E_0805-MFG]  (hidden comment: JR0805X35E)
R403  Res_ohm: 0  [FP-JR0805X35E_0805-MFG]  (hidden comment: JR0805X35E)
R404  Res_ohm: 0  [FP-JR0805X35E_0805-MFG]  (hidden comment: JR0805X35E)
R405  Res_ohm: 0  [FP-JR0805X35E_0805-MFG]  (hidden comment: JR0805X35E)
R406  value 100  [FP-RMCF0402FT100R_0402-MFG]  (hidden comment: RMCF0402FT100R)
R407  ValueDisplayed: 1.00k  [0402]  (hidden comment: MCR01MZPF1001)
RT400  B59751B0120A070  [TDK_B751]  (value not drawn)
U400  LM5050MK-1/NOPB  [DDC0006A_N]

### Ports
3V3 (in), 5V (in), 12V (in), A0 (in), A1 (in), A2 (in), BBU_ISHARE (in), CAN_H (in), CAN_L (in), COMP (in), COMP_DIR (out), CS+_total_charge_current_battery (out), CS-_total_charge_current_battery (out), DISCH_SS (out), FB_DIR (out), MODE (out), PSKILL (in), PWM1H_SYNC_0C (in), PWM1H_SYNC_60C (in), PWM1H_SYNC_120C (in), PWM1H_SYNC_180C (in), PWM1H_SYNC_240C (in), PWM1H_SYNC_300C (in), SGND (in), SHELF_ADDR0 (in), SHELF_ADDR1 (in), SHELF_ADDR2 (in), SHELF_ADDR3 (in), SYS_AC_LOSS_1 (in), SYS_AC_LOSS_2 (in), SYS_BBU_ALERT (in), SYS_BBU_RESET (in), SYS_PLS_LOP (in), SYS_Present_L (in), SYS_PULSE_MGMT_1 (in), SYS_RS485+ (in), SYS_RS485- (in), SYS_SOH_L (in), SYS_SYNC_START2_L (in), SYS_SYNC_START_L (in), UC_AD_ICS_1ph (out), UC_AD_ICS_2ph (out), UC_AD_ICS_3ph (out), UC_AD_ICS_4ph (out), UC_AD_ICS_5ph (out), UC_AD_ICS_6ph (out), UC_COMP_DIR (out), UC_COMP_DIR_AUX (out), UC_En_Disable (in), UC_En_Disable_AUX (out), UC_FAN_CLK (in), UC_FAN_PWM (in), UC_FB_DIR (out), UC_MODE (out), UC_MODE_AUX (out), UC_ORING_AUX (in), UC_ORING_EN (in), UC_SYS_PMBUS_SCL (in), UC_SYS_PMBUS_SDA (in), UC_VFB_DIR_AUX (out), VAUX (in), VBUS1 (in), VBUS_SENSE+ (in), VBUS_SENSE- (in), VFB (in), VORING1 (in), VORING (in)

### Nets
SGND: C400.1 C401.1 C402.1 C403.1 C404.2 C405.2 D400.2(A) Q400.2(S) Q401.2(S) Q402.2(S) R401.1 R403.1 R405.1 U400.2(GND)  [also labelled VBAT-]
COMP_DIR: R400.2 ; port COMP_DIR
FB_DIR: R402.2 ; port FB_DIR
MODE: R404.2 ; port MODE
ORING_GATE: Q403.9(Gate) U400.5(GATE)
UC_COMP_DIR: Q400.1(G) ; port UC_COMP_DIR
UC_FB_DIR: Q401.1(G) ; port UC_FB_DIR
UC_MODE: Q402.1(G) ; port UC_MODE
UC_ORING_AUX: R407.1 ; port UC_ORING_AUX
VAUX: C404.1 D400.1(K) Q403.1-2-3-4(Source) RT400.1 U400.4(IN) ; port VAUX
VORING: Q403.5-6-7-8(Drain) R406.2 RT400.2 U400.6(OUT) ; port VORING
NetC400_2: C400.2 Q400.3(D) R400.1 R401.2
NetC401_2: C401.2 Q401.3(D) R402.1 R403.2
NetC402_2: C402.2 Q402.3(D) R404.1 R405.2
NetC403_2: C403.2 R406.1 U400.1(VS)
NetC405_1: C405.1 R407.2 U400.3(OFF)

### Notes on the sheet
- Mainboard Connection
- Connection with Power Module (6 Phases)
- To TOP
- Power Module 1
- Power Module 2
- Power Module 3
- Power Module 4
- Power Module 5
- Power Module 6
- Connection with Aux Power card
- (near RT400) AUX ORING
- Power Module AUX
- SHELF Connections
- E1
- D1
- C1
- B1
- A1
- E2
- E3
- E4
- D2
- D3
- D4
- C2
- C3
- C4
- B2
- B3
- B4
- A2
- A3
- A4
- NA
- E5
- E6
- D5
- D6
- C5
- C6
- B5
- B6
- A5
- A6
- Connection with Oring card
- ORING board
- To be updated when the schematics symbol has been created
- Labels drawn without touching a wire or pin: SGND

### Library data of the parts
C400-C402 = CMP-0115312-1: as C230 on sheet PMP41155_Main_Control
C403 = CMP-0097294-1: 0.1 µF ±10% 100V Ceramic Capacitor X7R 0603 (1608 Metric); Manufacturer: Wurth Electronics; TempCo: 15%; SizeZ_mm: 0.87mm; Value: 100nF; AEC Qualified: No
C404 = CMP-0861070-2: CAP, CERM, 1 µF, 100 V,+/- 10%, X7R, AEC-Q200 Grade 1, 0805; Manufacturer: AVX; SizeZ_mm: 1.5; Polarized: N; TaMax_C: 125°C; TaMin_C: -55°C; Value: 1uF; AEC Qualified: Y; U/M: EA; AEC Grade: 1; Cap_Case: 0805; SizeX_mm: 2; SizeArea_mm2: 2.5; SizeAreaWB_mm2: 6.75; AEC Category: Q200; SizeY_mm: 1.25
C405 = CMP-0007404-5: CAP, CERM, 0.1 uF, 25 V, +/- 10%, X7R, 0603; Manufacturer: MuRata; TaMin_C: -55°C; Polarized: N; SizeAreaWB_mm2: 4.68; Value1: Unknown; U/M: EA; Value: 0.1uF; TaMax_C: 125°C; SizeZ_mm: 1; SizeX_mm: 1.6; SizeY_mm: 0.8; Value2: 25V; SizeArea_mm2: 1.28; AEC Category: Q200; MFG_Status: TI_Obsolete
D400 = CMP-0028394-2: Diode, Schottky, 80 V, 1 A, SMB; Manufacturer: Diodes Inc.; Value2: 0.79V; Value1: 1A; TJmax_C: 150°C; SizeY_mm: 3.81; SizeX_mm: 5.6; Green_REACh: Incomplete; Value: 80V; SizeZ_mm: 2.6; SizeArea_mm2: 21.336; Vf_V: 790mV; RJC_CperW: 25; Green_Lifecycle: Not Set; SizeAreaWB_mm2: 44.156; AEC Category: Q101
Q400-Q402 = CMP-0043768-1: as Q207 on sheet PMP41155_Main_Control
Q403 = CMP-0122332-1: N-Channel 80 V 31A (Ta), 323A (Tc) 3W (Ta), 333W (Tc) Surface Mount PG-TTFN-9-U02; Manufacturer: Infineon; AEC Qualified: No; QgTyp_nC: 106nC @ 10V; Rdson45_ohm: 1.4m; SizeZ_mm: 1.1mm; VdsMax_V: 1V; Vgs_V: 20V; ChMode: False; Drain To Source Breakdown Voltage: 80V; Input Capacitace At Vds: 7100pF @ 40V; Number Of Channels: 1; Pulse Drain Current: 1292A; Reverse Recovery Charge: 71nC; Reverse Recovery Time: 48ns; Rthja Max: 50°C/W; Threshold Vgs Max: 3.8V; Threshold Vgs Min: 2.2V; TJmax_C: +175°C; Transconductance: 140S; Turn Off Delay Time: 29ns; Turn On Delay Time: 15ns; Typ Forward Diode Voltage: 0.82V
R400-R405 = CMP-0096818-1: as R260 on sheet PMP41155_Main_Control
R406 = CMP-0094733-1: 100Ω ±1% 0.063W 0402 Thick Film Chip Resistor AEC-Q200 compliant; Manufacturer: Stackpole Electronics; AEC Grade: Grade 0; Power_W: 63mW; TempCo: 100ppm/°C; VDC_V: 50V; SizeZ_mm: 0.35mm; AEC Qualified: Yes
R407 = CMP-0026716-1: RES, 1.00 k, 1%, 0.063 W, 0402; Manufacturer: Rohm; Power_W: 63mW; TempCo: 100 ppm/C; Value_Code: 1k00; U/M: EA; Value: 1.00k; EIA_Code: E96; Res_ohm: 1k; SizeX_mm: 1; SizeY_mm: 0.5; SizeZ_mm: 0.6; Value2: 0.063W; AEC Qualified: N; VDC_V: 50V; AEC Category: Q200
RT400 = CMP-0002562-3: Thermistor NTC, 50 ohm, 25%, D12.5xH16.5mm; Manufacturer: TDK; Value: 50; TaMin_C: -40°C; TaMax_C: 125°C; U/M: EA; MFG_Status: TI_Obsolete
U400 = CMP-0066129-2: High Side OR-ing FET Controller, DDC0006A (SOT-23-T-6); Manufacturer: Texas Instruments; SizeZ_mm: 0.87; SizeX_mm: 1.65; SizeY_mm: 2.95; SizeArea_mm2: 4.8675; CompType: IC; U/M: EA; SizeAreaWB_mm2: 10.4675

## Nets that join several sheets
SGND: PMP41155_Main (5 pins), PMP41155_Main_Control 2 (41 pins), PMP41155_Main_Control 1 (38 pins), PMP41155_Main_Control (42 pins), PMP41155_Main_Connection (14 pins)
3V3: PMP41155_Main_Control 2 (9 pins), PMP41155_Main_Control 1 (29 pins), PMP41155_Main_Control (24 pins)
12V: PMP41155_Main_Control 2 (C202.1 C203.2 R207.1 U201.4), PMP41155_Main_Control (R245.2)
CS+_total_discharge_current_bus: PMP41155_Main (R306.1), PMP41155_Main_Control 2 (R204.2)
CS-_total_discharge_current_bus: PMP41155_Main (R307.1), PMP41155_Main_Control 2 (R206.2)
UC_AD_BBU_ISHARE: PMP41155_Main_Control 2 (C219.2 R215.2 R217.2), PMP41155_Main_Control (J202.24)
UC_AD_Total_Charge_Current_VBattery: PMP41155_Main_Control 2 (C216.1 R212.2), PMP41155_Main_Control (J202.34)
UC_AD_Total_Discharge_Current_VBus: PMP41155_Main_Control 2 (C208.1 R205.2), PMP41155_Main_Control (J202.28)
UC_AD_VBAT_SENSE: PMP41155_Main_Control 2 (R224.1 R227.2), PMP41155_Main_Control (J202.36)
UC_AD_VORING: PMP41155_Main_Control 2 (R226.1 R229.2), PMP41155_Main_Control (J202.37)
UC_AD_VORING1: PMP41155_Main_Control 2 (R225.1 R228.2), PMP41155_Main_Control (J202.39)
UC_BBU_ISHARE_PWM: PMP41155_Main_Control 2 (R208.1), PMP41155_Main_Control (J202.93)
UC_BMS_AUX_DIR: PMP41155_Main_Control 1 (C421.2 J400.7), PMP41155_Main_Control (J203.152)
UC_BMS_AUX_ON: PMP41155_Main_Control 1 (J400.5 R446.1), PMP41155_Main_Control (J202.95)
UC_BMS_CHG_EN: PMP41155_Main_Control 1 (C422.2 J400.9), PMP41155_Main_Control (J203.151)
UC_BMS_DCH_EN: PMP41155_Main_Control 1 (C423.2 J400.8), PMP41155_Main_Control (J203.150)
UC_BMS_FAULT: PMP41155_Main_Control 1 (C424.2 J400.6), PMP41155_Main_Control (J203.121)
UC_BMS_PACK_ON: PMP41155_Main_Control 1 (J400.1 R449.1), PMP41155_Main_Control (J202.94)
UC_BMS_SCL: PMP41155_Main_Control 1 (C425.2 J400.4 R447.1), PMP41155_Main_Control (J202.73)
UC_BMS_SDA: PMP41155_Main_Control 1 (C426.2 J400.3 R448.1), PMP41155_Main_Control (J202.86)
UC_COMP_DIR: PMP41155_Main_Control (J202.55), PMP41155_Main_Connection (Q400.1)
UC_EEPROM_CLK: PMP41155_Main_Control 1 (R434.1 U402.6), PMP41155_Main_Control (J202.104)
UC_EEPROM_SIMO: PMP41155_Main_Control 1 (R433.1 U402.5), PMP41155_Main_Control (J202.100)
UC_EEPROM_SOMI: PMP41155_Main_Control 1 (R436.1 U402.2), PMP41155_Main_Control (J202.102)
UC_EEPROM_STE: PMP41155_Main_Control 1 (R429.1 U402.1), PMP41155_Main_Control (J203.126)
UC_FB_DIR: PMP41155_Main_Control (J202.52), PMP41155_Main_Connection (Q401.1)
UC_LED_BBU_OK: PMP41155_Main_Control 2 (Q201.1), PMP41155_Main_Control (J203.122)
UC_LED_EOL: PMP41155_Main_Control 2 (Q203.1), PMP41155_Main_Control (J203.169)
UC_LED_FAIL: PMP41155_Main_Control 2 (Q204.1), PMP41155_Main_Control (J202.103)
UC_LED_LOW_V: PMP41155_Main_Control 2 (Q202.1), PMP41155_Main_Control (J202.89)
UC_MODE: PMP41155_Main_Control (J202.56), PMP41155_Main_Connection (Q402.1)
UC_ORING_AUX: PMP41155_Main_Control (J203.153), PMP41155_Main_Connection (R407.1)
UC_SYS_AC_LOSS_1: PMP41155_Main_Control 1 (R454.1), PMP41155_Main_Control (J202.79)
UC_SYS_AC_LOSS_2: PMP41155_Main_Control 1 (R442.1), PMP41155_Main_Control (J202.80)
UC_SYS_BBU_A0: PMP41155_Main_Control 1 (R415.1), PMP41155_Main_Control (J203.145)
UC_SYS_BBU_A1: PMP41155_Main_Control 1 (R426.1), PMP41155_Main_Control (J203.129)
UC_SYS_BBU_A2: PMP41155_Main_Control 1 (R441.1), PMP41155_Main_Control (J203.134)
UC_SYS_BBU_RESET_H: PMP41155_Main_Control 1 (R453.1), PMP41155_Main_Control (J203.124)
UC_SYS_Present_L: PMP41155_Main_Control 1 (R427.1), PMP41155_Main_Control (J203.178)
UC_SYS_PS_KILL: PMP41155_Main_Control 1 (R416.1), PMP41155_Main_Control (J202.88)
UC_SYS_PULSE_MGMT_1: PMP41155_Main_Control 1 (R417.1), PMP41155_Main_Control (J202.81)
UC_SYS_SHELF_ADDR_A0: PMP41155_Main_Control 1 (R414.1), PMP41155_Main_Control (J202.105)
UC_SYS_SHELF_ADDR_A1: PMP41155_Main_Control 1 (R425.1), PMP41155_Main_Control (J202.107)
UC_SYS_SHELF_ADDR_A2: PMP41155_Main_Control 1 (R440.1), PMP41155_Main_Control (J202.109)
UC_SYS_SHELF_ADDR_A3: PMP41155_Main_Control 1 (R455.1), PMP41155_Main_Control (J203.127)
UC_TA100_CLK: PMP41155_Main_Control 1 (U401.6), PMP41155_Main_Control (J203.130)
UC_TA100_RESET: PMP41155_Main_Control 1 (R412.1 U401.2), PMP41155_Main_Control (J203.143)
UC_TA100_SIMO: PMP41155_Main_Control 1 (U401.5), PMP41155_Main_Control (J203.125)
UC_TA100_SOMI: PMP41155_Main_Control 1 (U401.7), PMP41155_Main_Control (J202.77)
UC_TA100_STE: PMP41155_Main_Control 1 (R413.1 U401.1), PMP41155_Main_Control (J203.131)
Vbattery_DAC: PMP41155_Main_Control 2 (R271.2), PMP41155_Main_Control (J202.14)
Vbus_DAC: PMP41155_Main_Control 2 (R270.2), PMP41155_Main_Control (J202.9)
VORING: PMP41155_Main (6 pins), PMP41155_Main_Control 2 (R219.2 R222.2), PMP41155_Main_Connection (Q403.5-6-7-8 R406.2 RT400.2 U400.6)
VORING1: PMP41155_Main (8 pins), PMP41155_Main_Control 2 (R221.2)

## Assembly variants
001: all parts fitted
